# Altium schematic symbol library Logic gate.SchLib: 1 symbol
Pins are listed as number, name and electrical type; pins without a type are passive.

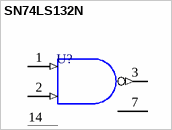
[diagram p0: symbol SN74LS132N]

## SN74LS132N
designator U?
Quadruple 2-Input Positive-NAND Schmitt Trigger
pins: 1 A (in), 2 A (in), 3 Y (out), 7 GND (power) hidden to GND, 14 VCC (power) hidden to VCC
